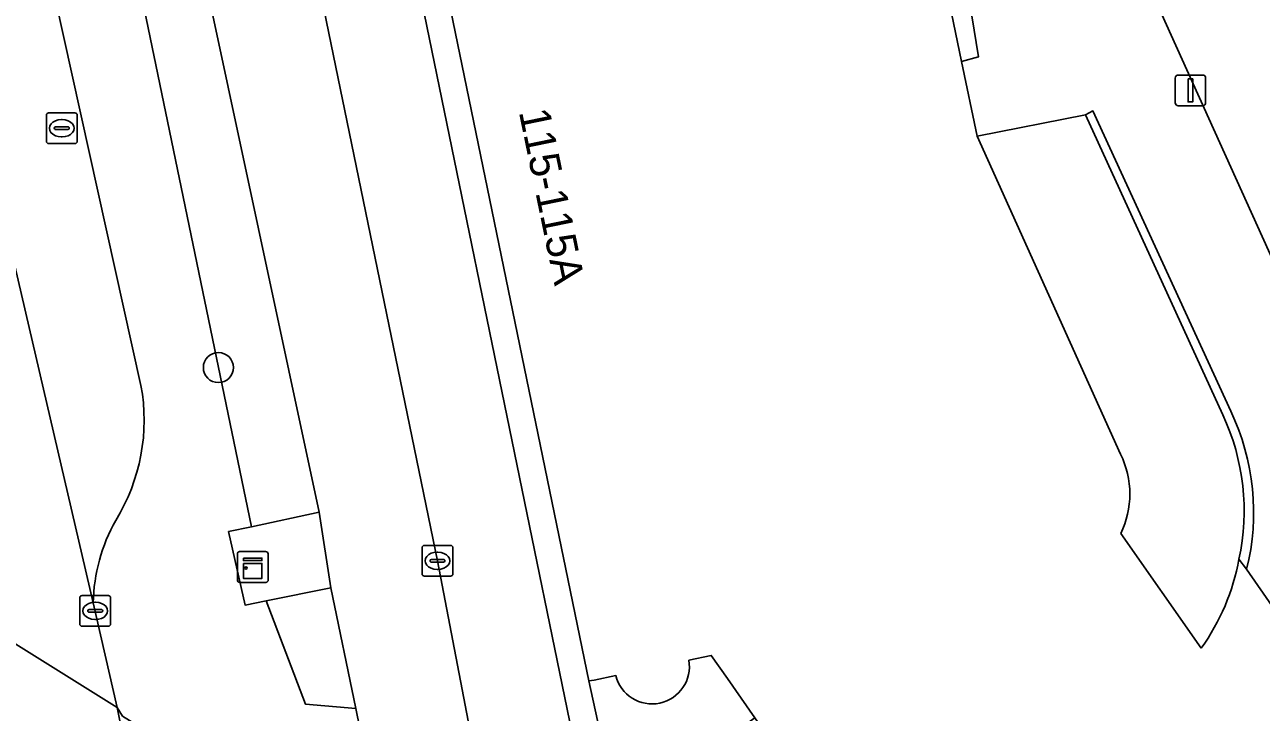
# Model space of a CAD drawing. Extents: x 163008 to 163854, y 382777 to 383982.
# Drawn here: x 163125.13 to 163165.24, y 383635.41 to 383657.73 of the extents above; entities that cross this region are included whole.
import ezdxf

# ---------------------------------------------------------------- set-up
doc = ezdxf.new("R2010")
doc.units = 0
for name, color, linetype in [('IMGEO_Berm_groen', 7, 'Continuous'), ('IMGEO_Boom', 7, 'Continuous'), ('IMGEO_Erf', 7, 'Continuous'), ('IMGEO_Fietspad_open', 7, 'Continuous'), ('IMGEO_Grasland_overig', 7, 'Continuous'), ('IMGEO_Groenvoorziening', 7, 'Continuous'), ('IMGEO_Kast', 7, 'Continuous'), ('IMGEO_Kolk', 7, 'Continuous'), ('IMGEO_Lichtmast', 7, 'Continuous'), ('IMGEO_Muur', 7, 'Continuous'), ('IMGEO_Pand', 7, 'Continuous'), ('IMGEO_Pand_nummerreeks', 7, 'Continuous'), ('IMGEO_Rijbaan_lokaal_open', 7, 'Continuous'), ('IMGEO_Rijbaan_regionaal_gesloten', 7, 'Continuous'), ('IMGEO_Rioolput', 7, 'Continuous'), ('IMGEO_Terreindeel_open', 7, 'Continuous'), ('IMGEO_Voetpad_gesloten', 7, 'Continuous'), ('IMGEO_Voetpad_open', 7, 'Continuous')]:
    doc.layers.add(name, color=color, linetype=linetype)

msp = doc.modelspace()

# ---------------------------------------------------------------- linework, layer by layer
at = {"layer": 'IMGEO_Berm_groen'}
for points in [[(163136.785, 383630.758), (163136.803, 383630.948), (163135.865, 383635.53), (163134.238, 383635.67), (163132.962, 383639.024), (163132.275, 383638.887), (163131.741, 383641.272), (163132.489, 383641.432), (163127.806, 383664.072)], [(163125.832, 383659.87), (163128.9, 383646.018)], [(163127.351, 383638.961), (163128.13, 383635.558), (163128.302, 383635.284), (163136.003, 383630.509)]]:
    msp.add_lwpolyline(points, dxfattribs=at)
for centre, radius, start, end in [((163122.822, 383644.89), 6.182, 328.2568, 10.5102), ((163133.096, 383638.836), 5.746, 150.8179, 178.7551)]:
    msp.add_arc(centre, radius, start, end, dxfattribs=at)
at = {"layer": 'IMGEO_Boom'}
msp.add_circle((163131.412, 383646.599), 0.489, dxfattribs=at)
at = {"layer": 'IMGEO_Erf'}
msp.add_lwpolyline([(163196.514, 383684.3), (163157.902, 383673.76), (163157.928, 383673.599), (163157.761, 383673.548), (163161.815, 383658.517), (163167.561, 383645.782), (163172.328, 383647.292), (163174.18, 383647.878), (163175.016, 383644.78), (163177.382, 383645.538), (163177.904, 383643.906), (163178.645, 383644.143), (163181.34, 383645.006), (163180.958, 383646.153), (163186.707, 383648.069), (163186.868, 383647.585), (163192.711, 383649.533), (163192.137, 383651.346), (163198.048, 383653.316)], dxfattribs=at)
at = {"layer": 'IMGEO_Fietspad_open'}
for points in [[(163133.616, 383670.772), (163129.367, 383666.746), (163129.662, 383665.369), (163129.76, 383664.91), (163134.679, 383641.902), (163135.064, 383639.444), (163135.865, 383635.53), (163136.803, 383630.948), (163137.278, 383627.327)], [(163140.87, 383628.079), (163138.518, 383640.326), (163133.93, 383662.62), (163132.87, 383667.8)]]:
    msp.add_lwpolyline(points, dxfattribs=at)
at = {"layer": 'IMGEO_Grasland_overig'}
msp.add_lwpolyline([(163136.465, 383666.013), (163143.054, 383633.923), (163143.938, 383634.098), (163143.424, 383636.43), (163137.52, 383665.124), (163153.077, 383668.348), (163154.091, 383663.452), (163155.521, 383656.535), (163156.064, 383656.685), (163154.631, 383665.551), (163153.823, 383669.608), (163138.679, 383666.445)], close=True, dxfattribs=at)
at = {"layer": 'IMGEO_Groenvoorziening'}
for points in [[(163134.679, 383641.902), (163129.76, 383664.91), (163127.806, 383664.072), (163132.489, 383641.432)], [(163135.064, 383639.444), (163132.962, 383639.024), (163134.238, 383635.67), (163135.865, 383635.53)]]:
    msp.add_lwpolyline(points, close=True, dxfattribs=at)
at = {"layer": 'IMGEO_Kast'}
for p, q in [((163132.026, 383639.7), (163132.026, 383640.541)), ((163132.026, 383640.541), (163132.026, 383639.7)), ((163132.101, 383640.625), (163132.942, 383640.625)), ((163132.942, 383640.625), (163132.101, 383640.625)), ((163133.026, 383640.55), (163133.026, 383639.709)), ((163133.026, 383639.709), (163133.026, 383640.55)), ((163132.951, 383639.625), (163132.11, 383639.625)), ((163132.11, 383639.625), (163132.951, 383639.625))]:
    msp.add_line(p, q, dxfattribs=at)
for points in [[(163132.221, 383640.415), (163132.821, 383640.415), (163132.821, 383640.33), (163132.221, 383640.33), (163132.221, 383640.415)], [(163132.221, 383640.24), (163132.821, 383640.24), (163132.821, 383639.751), (163132.221, 383639.751), (163132.221, 383640.24)]]:
    msp.add_lwpolyline(points, dxfattribs=at)
msp.add_circle((163132.305, 383640.089), 0.0377, dxfattribs=at)
for centre, start, end in [((163132.104, 383640.547), 92.4484, 184.2845), ((163132.104, 383640.547), 92.4484, 184.2845), ((163132.948, 383640.547), 2.4484, 94.2845), ((163132.948, 383640.547), 2.4484, 94.2845), ((163132.104, 383639.703), 182.4484, 274.2845), ((163132.104, 383639.703), 182.4484, 274.2845), ((163132.948, 383639.703), 272.4484, 4.2845), ((163132.948, 383639.703), 272.4484, 4.2845)]:
    msp.add_arc(centre, 0.0779, start, end, dxfattribs=at)
at = {"layer": 'IMGEO_Kolk'}
for p, q in [((163138.018, 383639.9), (163138.018, 383640.752)), ((163138.093, 383640.826), (163138.945, 383640.826)), ((163138.506, 383640.606), (163138.531, 383640.606)), ((163139.019, 383640.752), (163139.019, 383639.9)), ((163138.277, 383640.32), (163138.277, 383640.332)), ((163138.715, 383640.283), (163138.317, 383640.283)), ((163138.32, 383640.369), (163138.718, 383640.369)), ((163138.761, 383640.332), (163138.761, 383640.32)), ((163138.945, 383639.826), (163138.093, 383639.826)), ((163138.529, 383640.046), (163138.504, 383640.046)), ((163126.915, 383638.273), (163126.915, 383639.125)), ((163126.99, 383639.199), (163127.842, 383639.199)), ((163127.403, 383638.979), (163127.428, 383638.979)), ((163127.916, 383639.125), (163127.916, 383638.273)), ((163127.174, 383638.693), (163127.174, 383638.705)), ((163127.612, 383638.656), (163127.214, 383638.656)), ((163127.217, 383638.742), (163127.615, 383638.742)), ((163127.658, 383638.705), (163127.658, 383638.693)), ((163127.842, 383638.199), (163126.99, 383638.199)), ((163127.426, 383638.419), (163127.401, 383638.419))]:
    msp.add_line(p, q, dxfattribs=at)
for points in [[(163138.018, 383639.9), (163138.018, 383640.752)], [(163138.093, 383640.826), (163138.945, 383640.826)], [(163139.019, 383640.752), (163139.019, 383639.9)], [(163138.945, 383639.826), (163138.093, 383639.826)], [(163126.915, 383638.273), (163126.915, 383639.125)], [(163126.99, 383639.199), (163127.842, 383639.199)], [(163127.916, 383639.125), (163127.916, 383638.273)], [(163127.842, 383638.199), (163126.99, 383638.199)]]:
    msp.add_lwpolyline(points, dxfattribs=at)
for centre, radius, start, end in [((163138.095, 383640.75), 0.0765, 91.552, 178.448), ((163138.095, 383640.75), 0.0765, 91.552, 178.448), ((163138.943, 383640.75), 0.0765, 1.552, 88.448), ((163138.943, 383640.75), 0.0765, 1.552, 88.448), ((163138.317, 383640.329), 0.0403, 85.8775, 175.7526), ((163138.314, 383640.319), 0.0366, 178.938, 274.7102), ((163138.718, 383640.326), 0.043, 264.8664, 352.4533), ((163138.722, 383640.331), 0.0386, 1.7309, 96.639), ((163138.095, 383639.902), 0.0765, 181.552, 268.448), ((163138.095, 383639.902), 0.0765, 181.552, 268.448), ((163138.943, 383639.902), 0.0765, 271.552, 358.448), ((163138.943, 383639.902), 0.0765, 271.552, 358.448), ((163126.992, 383639.123), 0.0765, 91.552, 178.448), ((163126.992, 383639.123), 0.0765, 91.552, 178.448), ((163127.84, 383639.123), 0.0765, 1.552, 88.448), ((163127.84, 383639.123), 0.0765, 1.552, 88.448), ((163127.214, 383638.702), 0.0403, 85.8775, 175.7526), ((163127.211, 383638.692), 0.0366, 178.938, 274.7102), ((163127.615, 383638.699), 0.043, 264.8664, 352.4533), ((163127.619, 383638.704), 0.0386, 1.7309, 96.639), ((163126.992, 383638.275), 0.0765, 181.552, 268.448), ((163126.992, 383638.275), 0.0765, 181.552, 268.448), ((163127.84, 383638.275), 0.0765, 271.552, 358.448), ((163127.84, 383638.275), 0.0765, 271.552, 358.448)]:
    msp.add_arc(centre, radius, start, end, dxfattribs=at)
for centre, major_axis, ratio, start_param, end_param in [((163138.505, 383640.326), (-0.387, 0.002), 0.722429, 4.712389, 7.853982), ((163138.53, 383640.326), (-0.39, 0.002), 0.717154, 1.570796, 4.712389), ((163127.402, 383638.699), (-0.387, 0.002), 0.722429, 4.712389, 7.853982), ((163127.427, 383638.699), (-0.39, 0.002), 0.717154, 1.570796, 4.712389)]:
    msp.add_ellipse(centre, major_axis=major_axis, ratio=ratio, start_param=start_param, end_param=end_param, dxfattribs=at)
at = {"layer": 'IMGEO_Lichtmast'}
for p, q in [((163162.448, 383655.196), (163162.448, 383655.996)), ((163162.448, 383655.996), (163162.448, 383655.196)), ((163162.548, 383656.096), (163163.338, 383656.096)), ((163163.338, 383656.096), (163162.548, 383656.096)), ((163163.438, 383655.996), (163163.438, 383655.196)), ((163163.438, 383655.196), (163163.438, 383655.996)), ((163163.338, 383655.096), (163162.548, 383655.096)), ((163162.548, 383655.096), (163163.338, 383655.096))]:
    msp.add_line(p, q, dxfattribs=at)
msp.add_lwpolyline([(163162.868, 383655.971), (163163.018, 383655.971), (163163.018, 383655.221), (163162.868, 383655.221), (163162.868, 383655.971)], dxfattribs=at)
for centre, start, end in [((163162.548, 383655.996), 90, 180), ((163162.548, 383655.996), 90, 180), ((163163.338, 383655.996), 0, 90), ((163163.338, 383655.996), 360, 90), ((163162.548, 383655.196), 180, 270), ((163162.548, 383655.196), 180, 270), ((163163.338, 383655.196), 270, 0), ((163163.338, 383655.196), 270, 0)]:
    msp.add_arc(centre, 0.1, start, end, dxfattribs=at)
at = {"layer": 'IMGEO_Muur'}
for points in [[(163164.253, 383645.18), (163159.783, 383654.93), (163159.537, 383654.808), (163163.994, 383645.064)], [(163164.518, 383640.377), (163164.768, 383640.049)]]:
    msp.add_lwpolyline(points, dxfattribs=at)
for centre, radius, start, end in [((163157.296, 383641.942), 7.39, 347.7701, 24.9881), ((163157.346, 383641.895), 7.648, 346.0301, 25.4331)]:
    msp.add_arc(centre, radius, start, end, dxfattribs=at)
at = {"layer": 'IMGEO_Pand'}
for points in [[(163156.023, 383654.109), (163155.521, 383656.535), (163154.091, 383663.452), (163153.077, 383668.348), (163137.52, 383665.124), (163143.424, 383636.43), (163143.6, 383636.454), (163144.3, 383636.603)], [(163160.678, 383643.784), (163156.023, 383654.109)], [(163163.296, 383637.485), (163160.681, 383641.212)], [(163146.672, 383637.101), (163147.397, 383637.251), (163147.93, 383636.5), (163148.814, 383635.232), (163159.989, 383619.101), (163171.109, 383630.894), (163166.676, 383637.295), (163164.768, 383640.049), (163164.518, 383640.377)]]:
    msp.add_lwpolyline(points, dxfattribs=at)
for centre, radius, start, end in [((163158.059, 383642.495), 2.919, 333.9312, 26.2024), ((163157.409, 383641.677), 7.227, 324.549, 349.6385), ((163145.478, 383636.892), 1.213, 193.7705, 9.9435)]:
    msp.add_arc(centre, radius, start, end, dxfattribs=at)
at = {"layer": 'IMGEO_Rijbaan_lokaal_open'}
msp.add_lwpolyline([(163164.768, 383640.049), (163166.676, 383637.295), (163170.792, 383638.638), (163167.561, 383645.782), (163161.815, 383658.517), (163157.761, 383673.548), (163153.268, 383672.296), (163153.823, 383669.608), (163154.631, 383665.551), (163156.064, 383656.685), (163155.521, 383656.535), (163156.023, 383654.109), (163159.537, 383654.808), (163159.783, 383654.93), (163164.253, 383645.18)], dxfattribs=at)
msp.add_arc((163157.346, 383641.895), 7.648, 346.0301, 25.4331, dxfattribs=at)
at = {"layer": 'IMGEO_Rijbaan_regionaal_gesloten'}
for points in [[(163088.772, 383789.05), (163093.737, 383771.763), (163099.604, 383748.287), (163105.471, 383721.431), (163116.136, 383673.057), (163122.891, 383644.423), (163124.134, 383638.055), (163128.13, 383635.558), (163127.351, 383638.961), (163122.939, 383657.907), (163120.81, 383669.01), (163120.407, 383670.897), (163117.203, 383685.871), (163113.88, 383701.029), (163107.239, 383731.196), (163106.226, 383735.552), (163102.774, 383750), (163098.97, 383764.833), (163096.65, 383773.589), (163094.19, 383782.316), (163090.567, 383794.791)], [(163120.81, 383669.01), (163122.939, 383657.907), (163127.351, 383638.961)], [(163128.9, 383646.018), (163125.832, 383659.87)], [(163126.442, 383621.489), (163128.888, 383610.179), (163131.535, 383597.936), (163132.69, 383592.598), (163134.503, 383591.15), (163138.661, 383587.83), (163137.366, 383593.742), (163136.416, 383598.11), (163135.826, 383600.741), (163135.786, 383600.895), (163129.893, 383626.912), (163128.98, 383631.388), (163128.935, 383631.609), (163128.706, 383632.73), (163128.13, 383635.558), (163124.134, 383638.055), (163122.773, 383638.9), (163123.886, 383633.617), (163126.442, 383621.489)]]:
    msp.add_lwpolyline(points, dxfattribs=at)
for centre, radius, start, end in [((163122.822, 383644.89), 6.182, 328.2568, 10.5102), ((163133.096, 383638.836), 5.746, 150.8179, 178.7551)]:
    msp.add_arc(centre, radius, start, end, dxfattribs=at)
at = {"layer": 'IMGEO_Rioolput'}
for p, q in [((163125.83, 383653.942), (163125.83, 383654.794)), ((163125.905, 383654.868), (163126.757, 383654.868)), ((163126.318, 383654.648), (163126.343, 383654.648)), ((163126.831, 383654.794), (163126.831, 383653.942)), ((163126.089, 383654.362), (163126.089, 383654.374)), ((163126.527, 383654.325), (163126.129, 383654.325)), ((163126.132, 383654.411), (163126.53, 383654.411)), ((163126.573, 383654.374), (163126.573, 383654.362)), ((163126.757, 383653.868), (163125.905, 383653.868)), ((163126.341, 383654.088), (163126.316, 383654.088))]:
    msp.add_line(p, q, dxfattribs=at)
for points in [[(163125.83, 383653.942), (163125.83, 383654.794)], [(163125.905, 383654.868), (163126.757, 383654.868)], [(163126.831, 383654.794), (163126.831, 383653.942)], [(163126.757, 383653.868), (163125.905, 383653.868)]]:
    msp.add_lwpolyline(points, dxfattribs=at)
for centre, radius, start, end in [((163125.907, 383654.792), 0.0765, 91.552, 178.448), ((163125.907, 383654.792), 0.0765, 91.552, 178.448), ((163126.755, 383654.792), 0.0765, 1.552, 88.448), ((163126.755, 383654.792), 0.0765, 1.552, 88.448), ((163126.129, 383654.371), 0.0403, 85.8775, 175.7526), ((163126.126, 383654.361), 0.0366, 178.938, 274.7102), ((163126.53, 383654.368), 0.043, 264.8664, 352.4533), ((163126.534, 383654.373), 0.0386, 1.7309, 96.639), ((163125.907, 383653.944), 0.0765, 181.552, 268.448), ((163125.907, 383653.944), 0.0765, 181.552, 268.448), ((163126.755, 383653.944), 0.0765, 271.552, 358.448), ((163126.755, 383653.944), 0.0765, 271.552, 358.448)]:
    msp.add_arc(centre, radius, start, end, dxfattribs=at)
for centre, major_axis, ratio, start_param, end_param in [((163126.317, 383654.368), (-0.387, 0.002), 0.722429, 4.712389, 7.853982), ((163126.342, 383654.368), (-0.39, 0.002), 0.717154, 1.570796, 4.712389)]:
    msp.add_ellipse(centre, major_axis=major_axis, ratio=ratio, start_param=start_param, end_param=end_param, dxfattribs=at)
at = {"layer": 'IMGEO_Terreindeel_open'}
msp.add_lwpolyline([(163135.064, 383639.444), (163134.679, 383641.902), (163132.489, 383641.432), (163131.741, 383641.272), (163132.275, 383638.887), (163132.962, 383639.024)], close=True, dxfattribs=at)
at = {"layer": 'IMGEO_Voetpad_gesloten'}
for points in [[(163163.994, 383645.064), (163159.537, 383654.808), (163156.023, 383654.109), (163160.678, 383643.784)], [(163160.681, 383641.212), (163163.296, 383637.485)]]:
    msp.add_lwpolyline(points, dxfattribs=at)
for centre, radius, start, end in [((163157.296, 383641.942), 7.39, 347.7701, 24.9881), ((163158.059, 383642.495), 2.919, 333.9312, 26.2024), ((163157.409, 383641.677), 7.227, 324.549, 349.6385)]:
    msp.add_arc(centre, radius, start, end, dxfattribs=at)
at = {"layer": 'IMGEO_Voetpad_open'}
for points in [[(163200.537, 383617.916), (163192.599, 383615.406), (163171.045, 383608.592), (163165.49, 383613.872), (163159.989, 383619.101), (163159.054, 383618.417), (163147.862, 383634.546), (163144.401, 383631.977), (163143.938, 383634.098), (163143.054, 383633.923), (163136.465, 383666.013), (163135.19, 383672.222)], [(163132.87, 383667.8), (163133.93, 383662.62), (163138.518, 383640.326), (163140.87, 383628.079), (163141.612, 383624.451)], [(163144.3, 383636.603), (163143.6, 383636.454), (163143.424, 383636.43), (163143.938, 383634.098), (163144.401, 383631.977), (163147.862, 383634.546), (163148.814, 383635.232), (163147.93, 383636.5), (163147.397, 383637.251), (163146.672, 383637.101)], [(163128.302, 383635.284), (163128.13, 383635.558), (163128.706, 383632.73), (163128.935, 383631.609), (163128.98, 383631.388), (163129.137, 383631.305)]]:
    msp.add_lwpolyline(points, dxfattribs=at)
msp.add_arc((163145.478, 383636.892), 1.213, 193.7705, 9.9435, dxfattribs=at)

# ---------------------------------------------------------------- texts
at = {"layer": 'IMGEO_Pand_nummerreeks'}
msp.add_text('115-115A', height=1, rotation=281.6251, dxfattribs=at).set_placement((163141.154, 383654.905))

doc.saveas('drawing.dxf')
